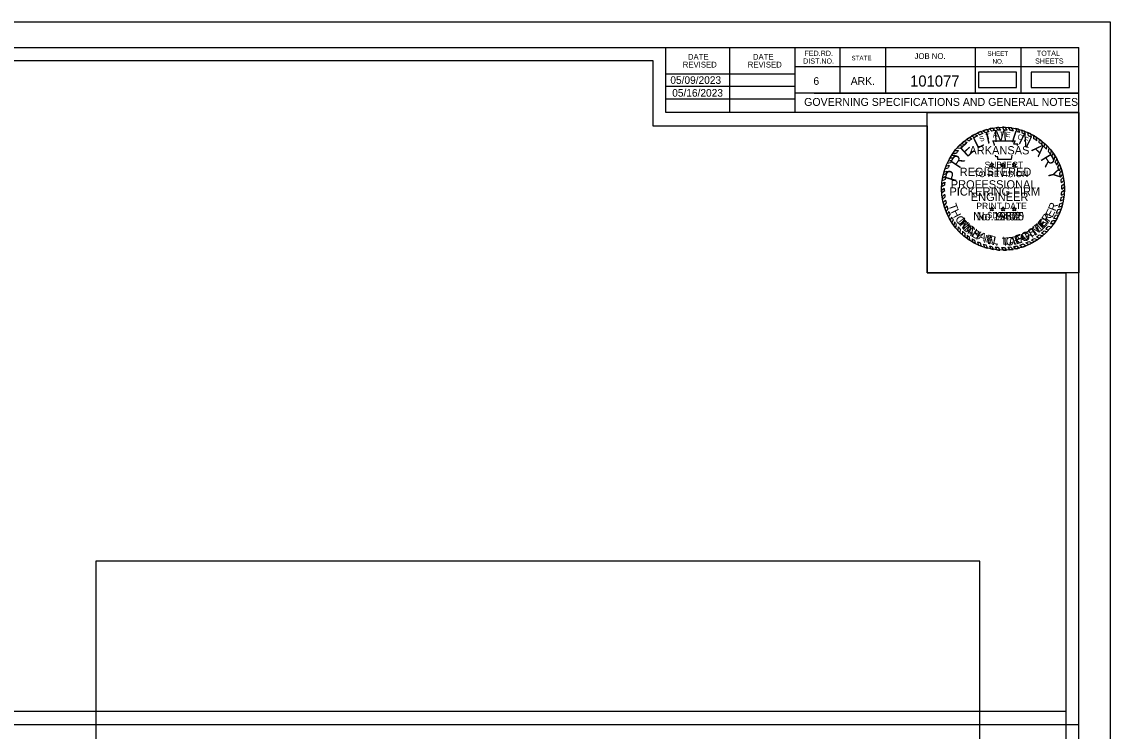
# Model space of a CAD drawing. Extents: x 1369900 to 1370234, y 380116 to 380330.
# Drawn here: x 1370068.5 to 1370233.6, y 380221.9 to 380329.6 of the extents above; entities that cross this region are included whole.
import ezdxf

# ---------------------------------------------------------------- set-up
doc = ezdxf.new("R2010")
doc.units = 0
for name, color, linetype in [('Default', 7, 'Continuous'), ('R_Border', 7, 'Continuous'), ('R_Border Notes', 7, 'Continuous'), ('R_Border Plan-Plan', 7, 'Continuous'), ('R_No Plot', 7, 'Continuous'), ('R_Revision Date Text', 7, 'Continuous'), ('STAMP_PE_CRAFTON', 7, 'Continuous'), ('STAMP_PE_FOSTER', 7, 'Continuous'), ('STAMP_PE_SEAL-INFO', 7, 'Continuous'), ('STAMP_PE_TAEGTMEYER', 7, 'Continuous'), ('STAMP_PE_TXT', 7, 'Continuous'), ('STAMP_PRELIMINARY', 7, 'Continuous')]:
    doc.layers.add(name, color=color, linetype=linetype)

msp = doc.modelspace()

# ---------------------------------------------------------------- linework, layer by layer
at = {"layer": 'Default'}
for points in [[(1370213.62, 380319.59), (1370219.42, 380319.59), (1370219.42, 380321.88), (1370213.62, 380321.88)], [(1370221.64, 380319.6), (1370227.44, 380319.6), (1370227.44, 380321.89), (1370221.64, 380321.89)], [(1370079.79, 380198.13), (1370213.84, 380198.13), (1370213.84, 380247.72), (1370079.79, 380247.72)]]:
    msp.add_lwpolyline(points, close=True, dxfattribs=at)
at = {"layer": 'R_Border'}
for p, q in [((1369912.68, 380325.66), (1370228.86, 380325.66)), ((1370166.22, 380315.78), (1370166.22, 380325.66)), ((1370175.9, 380315.78), (1370175.9, 380325.66)), ((1370185.76, 380325.66), (1370185.76, 380315.78)), ((1370192.6, 380325.66), (1370192.6, 380318.72)), ((1370199.54, 380325.66), (1370199.54, 380318.72)), ((1370213.12, 380325.66), (1370213.12, 380318.72)), ((1370220.06, 380325.66), (1370220.06, 380318.72)), ((1370228.86, 380120.2), (1370228.86, 380325.66)), ((1370228.86, 380322.72), (1370185.76, 380322.72)), ((1370228.86, 380322.74), (1370228.86, 380322.74)), ((1370166.22, 380321.64), (1370185.76, 380321.64)), ((1370166.22, 380319.78), (1370185.76, 380319.78)), ((1370166.22, 380317.84), (1370185.76, 380317.84)), ((1370228.86, 380318.72), (1370185.76, 380318.72)), ((1370188.72, 380318.72), (1370228.86, 380318.72)), ((1370228.86, 380315.78), (1370166.22, 380315.78))]:
    msp.add_line(p, q, dxfattribs=at)
at = {"layer": 'R_Border Plan-Plan'}
msp.add_line((1369912.68, 380222.93), (1370228.86, 380222.93), dxfattribs=at)
at = {"layer": 'R_No Plot'}
for points in [[(1369900.27, 380329.55), (1370233.61, 380329.55), (1370233.61, 380116.21), (1369900.27, 380116.21)], [(1370226.86, 380224.93), (1369914.68, 380224.93), (1369914.68, 380323.66), (1370164.22, 380323.66), (1370164.22, 380313.78), (1370181.76, 380313.78), (1370205.86, 380313.78), (1370205.86, 380291.44), (1370226.86, 380291.44)], [(1369914.68, 380323.66), (1370164.22, 380323.66), (1370164.22, 380313.78), (1370181.76, 380313.78), (1370205.86, 380313.78), (1370205.86, 380291.44), (1370226.86, 380291.44), (1370226.86, 380122.2), (1369914.68, 380122.2)], [(1370205.86, 380315.78), (1370228.86, 380315.78), (1370228.86, 380291.44), (1370205.86, 380291.44)]]:
    msp.add_lwpolyline(points, close=True, dxfattribs=at)
at = {"layer": 'STAMP_PE_SEAL-INFO'}
for p, q in [((1370213.46, 380312.69), (1370213.85, 380312.41)), ((1370213.97, 380312.9), (1370214.27, 380312.58)), ((1370214.32, 380313.03), (1370214.7, 380312.73)), ((1370214.91, 380313.21), (1370215.2, 380312.87)), ((1370215.3, 380313.31), (1370215.65, 380312.97)), ((1370215.78, 380313.41), (1370216.08, 380313.04)), ((1370216.3, 380313.48), (1370216.58, 380313.1)), ((1370217.03, 380313.13), (1370216.72, 380313.52)), ((1370217.53, 380313.13), (1370217.25, 380313.54)), ((1370217.99, 380313.11), (1370217.73, 380313.53)), ((1370218.49, 380313.06), (1370218.2, 380313.5)), ((1370218.92, 380312.99), (1370218.66, 380313.45)), ((1370219.48, 380312.88), (1370219.31, 380313.34)), ((1370219.88, 380312.77), (1370219.72, 380313.24)), ((1370220.33, 380312.62), (1370220.19, 380313.1)), ((1370220.75, 380312.46), (1370220.61, 380312.96)), ((1370221.21, 380312.26), (1370221.11, 380312.75)), ((1370211.06, 380311.09), (1370211.52, 380310.95)), ((1370211.4, 380311.39), (1370211.93, 380311.29)), ((1370211.78, 380311.72), (1370212.23, 380311.51)), ((1370212.2, 380311.98), (1370212.64, 380311.78)), ((1370212.59, 380312.23), (1370213.02, 380312)), ((1370213.03, 380312.48), (1370213.5, 380312.25)), ((1370215.83, 380311.51), (1370219.18, 380311.51)), ((1370215.95, 380311.2), (1370215.83, 380311.51)), ((1370216.06, 380310.9), (1370215.95, 380311.2)), ((1370219.18, 380311.51), (1370218.95, 380311.02)), ((1370218.95, 380311.02), (1370219.58, 380311.02)), ((1370219.58, 380311.02), (1370219.44, 380310.79)), ((1370221.66, 380312.03), (1370221.57, 380312.53)), ((1370222.05, 380311.8), (1370222.01, 380312.3)), ((1370222.48, 380311.51), (1370222.45, 380312.03)), ((1370222.84, 380311.25), (1370222.88, 380311.73)), ((1370223.29, 380310.87), (1370223.31, 380311.4)), ((1370223.6, 380310.58), (1370223.67, 380311.08)), ((1370209.54, 380309.29), (1370210.06, 380309.33)), ((1370209.78, 380309.64), (1370210.28, 380309.63)), ((1370210.05, 380310.01), (1370210.6, 380310.03)), ((1370210.4, 380310.42), (1370210.92, 380310.38)), ((1370210.72, 380310.76), (1370211.27, 380310.72)), ((1370216.07, 380310.79), (1370216.06, 380310.9)), ((1370216.26, 380309.08), (1370216.23, 380309.3)), ((1370218.69, 380309.3), (1370218.62, 380308.99)), ((1370223.96, 380310.21), (1370224.03, 380310.73)), ((1370224.23, 380309.89), (1370224.37, 380310.36)), ((1370224.56, 380309.47), (1370224.69, 380309.97)), ((1370224.78, 380309.16), (1370224.96, 380309.62)), ((1370208.69, 380307.65), (1370209.2, 380307.8)), ((1370208.88, 380308.08), (1370209.38, 380308.19)), ((1370209.06, 380308.47), (1370209.56, 380308.54)), ((1370209.29, 380308.89), (1370209.78, 380308.91)), ((1370216.57, 380309.08), (1370216.26, 380309.08)), ((1370216.57, 380308.65), (1370216.57, 380309.08)), ((1370218.6, 380308.65), (1370216.57, 380308.65)), ((1370218.62, 380308.99), (1370218.6, 380308.65)), ((1370225.09, 380308.66), (1370225.27, 380309.15)), ((1370225.29, 380308.3), (1370225.51, 380308.74)), ((1370225.52, 380307.81), (1370225.74, 380308.3)), ((1370225.66, 380307.47), (1370225.92, 380307.91)), ((1370208.64, 380306.09), (1370208.18, 380305.84)), ((1370208.28, 380306.33), (1370208.75, 380306.53)), ((1370208.38, 380306.74), (1370208.86, 380306.91)), ((1370208.54, 380307.24), (1370209.03, 380307.38)), ((1370225.85, 380306.93), (1370226.12, 380307.4)), ((1370225.96, 380306.56), (1370226.25, 380307.01)), ((1370226.09, 380306), (1370226.41, 380306.45)), ((1370226.16, 380305.62), (1370226.52, 380305.98)), ((1370208.46, 380304.77), (1370208.04, 380304.51)), ((1370208.5, 380305.19), (1370208.06, 380304.91)), ((1370208.56, 380305.63), (1370208.11, 380305.41)), ((1370226.23, 380305.11), (1370226.6, 380305.45)), ((1370226.26, 380304.69), (1370226.65, 380304.99)), ((1370226.27, 380304.18), (1370226.68, 380304.5)), ((1370208.45, 380304.27), (1370208.04, 380303.94)), ((1370208.45, 380303.87), (1370208.06, 380303.54)), ((1370208.49, 380303.37), (1370208.12, 380303.01)), ((1370208.54, 380302.94), (1370208.18, 380302.57)), ((1370226.17, 380302.88), (1370226.62, 380303.1)), ((1370226.22, 380303.27), (1370226.66, 380303.52)), ((1370226.26, 380303.77), (1370226.68, 380304.05)), ((1370208.62, 380302.48), (1370208.28, 380302.12)), ((1370208.71, 380302.06), (1370208.4, 380301.65)), ((1370208.83, 380301.62), (1370208.54, 380301.2)), ((1370208.98, 380301.19), (1370208.69, 380300.78)), ((1370225.69, 380301.05), (1370226.17, 380301.18)), ((1370225.83, 380301.43), (1370226.32, 380301.63)), ((1370225.97, 380301.93), (1370226.45, 380302.13)), ((1370226.08, 380302.38), (1370226.54, 380302.57)), ((1370209.14, 380300.77), (1370208.88, 380300.35)), ((1370209.31, 380300.38), (1370209.09, 380299.92)), ((1370209.55, 380299.93), (1370209.36, 380299.44)), ((1370209.78, 380299.52), (1370209.6, 380299.05)), ((1370224.87, 380299.42), (1370225.35, 380299.42)), ((1370225.04, 380299.7), (1370225.55, 380299.76)), ((1370225.32, 380300.2), (1370225.8, 380300.27)), ((1370225.48, 380300.54), (1370225.97, 380300.63)), ((1370209.99, 380299.21), (1370209.88, 380298.66)), ((1370210.27, 380298.82), (1370210.17, 380298.29)), ((1370210.57, 380298.44), (1370210.48, 380297.92)), ((1370210.87, 380298.1), (1370210.81, 380297.58)), ((1370211.2, 380297.78), (1370211.17, 380297.25)), ((1370223.59, 380297.84), (1370224.03, 380297.7)), ((1370223.84, 380298.1), (1370224.32, 380298.01)), ((1370224.23, 380298.53), (1370224.69, 380298.45)), ((1370224.53, 380298.93), (1370225.04, 380298.93)), ((1370211.54, 380297.47), (1370211.54, 380296.94)), ((1370211.9, 380297.17), (1370211.92, 380296.65)), ((1370212.24, 380296.92), (1370212.28, 380296.4)), ((1370212.67, 380296.64), (1370212.73, 380296.13)), ((1370213.02, 380296.43), (1370213.11, 380295.92)), ((1370213.5, 380296.19), (1370213.65, 380295.66)), ((1370221.28, 380296.22), (1370221.77, 380296)), ((1370221.69, 380296.43), (1370222.11, 380296.2)), ((1370222.11, 380296.67), (1370222.56, 380296.48)), ((1370222.45, 380296.9), (1370222.89, 380296.71)), ((1370222.91, 380297.24), (1370223.38, 380297.1)), ((1370223.18, 380297.47), (1370223.65, 380297.34)), ((1370213.87, 380296.02), (1370214.04, 380295.51)), ((1370214.36, 380295.82), (1370214.57, 380295.32)), ((1370214.77, 380295.69), (1370215, 380295.2)), ((1370215.28, 380295.55), (1370215.49, 380295.08)), ((1370215.68, 380295.47), (1370215.92, 380295.01)), ((1370216.18, 380295.38), (1370216.42, 380294.94)), ((1370216.61, 380295.34), (1370216.89, 380294.91)), ((1370217.1, 380295.31), (1370217.4, 380294.9)), ((1370217.56, 380295.31), (1370217.9, 380294.91)), ((1370218.08, 380295.33), (1370218.4, 380294.95)), ((1370218.52, 380295.38), (1370218.89, 380295.02)), ((1370218.96, 380295.45), (1370219.35, 380295.11)), ((1370219.45, 380295.55), (1370219.83, 380295.23)), ((1370219.91, 380295.68), (1370220.33, 380295.38)), ((1370220.41, 380295.84), (1370220.85, 380295.57)), ((1370220.82, 380296.01), (1370221.25, 380295.75))]:
    msp.add_line(p, q, dxfattribs=at)
for radius, start, end in [(9.32, 111.3124, 114.7026), (8.91, 110.3086, 113.1659), (9.32, 105.2339, 109.0352), (8.91, 104.0352, 107.3615), (9.32, 99.7525, 102.7765), (8.91, 98.258, 101.0329), (9.32, 93.9381, 96.5517), (8.91, 92.1102, 95.0367), (9.32, 87.7298, 90.6707), (8.91, 85.9628, 88.9097), (9.32, 81.9732, 84.8236), (8.91, 79.9264, 82.696), (9.32, 75.3125, 77.9426), (8.91, 73.5575, 76.2314), (9.32, 69.6061, 72.3058), (8.91, 67.6248, 70.504), (9.32, 63.1329, 66.2704), (9.32, 129.7326, 132.5376), (8.91, 127.5297, 130.9683), (9.32, 123.6199, 126.5906), (8.91, 121.9746, 125.11), (9.32, 117.6544, 120.8099), (8.91, 115.6869, 119.1583), (8.91, 61.1558, 64.3784), (9.32, 56.9003, 60.0942), (8.91, 54.9238, 58.2702), (8.91, 48.3016, 52.0395), (9.32, 50.3492, 53.7159), (9.32, 44.3405, 47.3929), (9.32, 147.0072, 149.899), (9.32, 141.6056, 144.4486), (8.91, 145.0197, 148.2104), (8.91, 139.301, 142.5873), (9.32, 135.4021, 138.3031), (8.91, 133.1331, 136.2562), (8.91, 42.2212, 45.5512), (8.91, 36.135, 39.5311), (9.32, 38.1247, 41.2316), (9.32, 31.9614, 35.4294), (9.32, 158.4077, 161.0701), (9.32, 152.864, 155.5189), (8.91, 156.3402, 159.2319), (8.91, 151.0315, 153.573), (8.91, 29.9032, 33.6645), (8.91, 23.7732, 27.2211), (9.32, 25.9391, 29.0125), (9.32, 19.9538, 23.3141), (9.32, 164.3068, 166.894), (8.91, 167.9048, 170.9039), (8.91, 162.4331, 165.0013), (8.91, 17.6802, 21.4251), (8.91, 11.5444, 15.2364), (9.32, 13.8421, 17.4447), (9.32, 7.5852, 10.8621), (9.32, 175.7409, 178.2066), (9.32, 170.0003, 172.6878), (8.91, 173.73, 176.4734), (8.91, 5.7599, 9.0606), (8.91, 359.7329, 3.0639), (9.32, 1.7215, 4.7268), (9.32, 181.7251, 184.1626), (9.32, 187.4204, 190.1927), (8.91, 179.6454, 182.2633), (8.91, 185.4539, 188.234), (8.91, 348.0778, 351.3435), (8.91, 353.8632, 357.1274), (9.32, 349.8305, 353.0885), (9.32, 355.7156, 358.9569), (9.32, 193.0369, 195.9973), (9.32, 198.8967, 201.6281), (8.91, 191.2274, 193.9858), (8.91, 196.9675, 199.8353), (8.91, 335.6038, 339.1858), (8.91, 341.777, 345.0925), (9.32, 337.3837, 340.9933), (9.32, 343.8925, 347.035), (9.32, 204.5479, 207.4328), (8.91, 202.7761, 205.4791), (9.32, 210.8636, 213.6571), (8.91, 208.7883, 211.7934), (8.91, 323.5851, 327.4407), (8.91, 329.5549, 333.2076), (9.32, 325.4405, 328.9872), (9.32, 331.4037, 334.9332), (9.32, 216.6115, 219.491), (8.91, 214.1838, 217.2747), (9.32, 222.48, 225.3801), (8.91, 220.3909, 223.3056), (8.91, 226.2494, 229.2407), (8.91, 310.7744, 314.3161), (8.91, 316.6531, 320.3711), (9.32, 318.2846, 321.8043), (9.32, 228.3665, 231.348), (8.91, 232.229, 234.9336), (9.32, 234.295, 236.9452), (8.91, 238.2223, 240.8353), (9.32, 240.1977, 242.8613), (8.91, 244.3204, 246.9486), (8.91, 292.8745, 296.1185), (8.91, 299.0768, 302.1724), (9.32, 300.621, 303.8703), (8.91, 304.823, 308.5143), (9.32, 306.3721, 310.208), (9.32, 312.4518, 315.6633), (9.32, 246.576, 249.1558), (8.91, 250.3491, 253.1216), (9.32, 252.5967, 255.3252), (8.91, 256.505, 259.1192), (9.32, 258.4433, 261.1398), (8.91, 262.3783, 265.2012), (9.32, 264.1978, 267.1009), (8.91, 268.3215, 271.277), (9.32, 270.2548, 273.3361), (8.91, 274.6157, 277.4486), (9.32, 276.4239, 279.4357), (8.91, 280.3459, 283.5814), (9.32, 282.3199, 285.3702), (8.91, 286.6423, 289.9783), (9.32, 288.5709, 291.9733), (9.32, 294.6481, 298.2166)]:
    msp.add_arc((1370217.36, 380304.22), radius, start, end, dxfattribs=at)
at = {"layer": 'STAMP_PE_TXT'}
for p, q in [((1370215.54, 380307.79), (1370215.34, 380307.93)), ((1370215.34, 380307.93), (1370215.59, 380307.93)), ((1370215.46, 380307.56), (1370215.54, 380307.79)), ((1370215.66, 380307.7), (1370215.46, 380307.56)), ((1370215.59, 380307.93), (1370215.66, 380308.17)), ((1370215.66, 380308.17), (1370215.74, 380307.93)), ((1370215.86, 380307.56), (1370215.66, 380307.7)), ((1370215.74, 380307.93), (1370215.98, 380307.93)), ((1370215.98, 380307.93), (1370215.78, 380307.79)), ((1370215.78, 380307.79), (1370215.86, 380307.56)), ((1370217.24, 380307.79), (1370217.04, 380307.93)), ((1370217.04, 380307.93), (1370217.28, 380307.93)), ((1370217.16, 380307.56), (1370217.24, 380307.79)), ((1370217.36, 380307.7), (1370217.16, 380307.56)), ((1370217.28, 380307.93), (1370217.36, 380308.17)), ((1370217.36, 380308.17), (1370217.44, 380307.93)), ((1370217.56, 380307.56), (1370217.36, 380307.7)), ((1370217.44, 380307.93), (1370217.68, 380307.93)), ((1370217.68, 380307.93), (1370217.48, 380307.79)), ((1370217.48, 380307.79), (1370217.56, 380307.56)), ((1370218.94, 380307.79), (1370218.74, 380307.93)), ((1370218.74, 380307.93), (1370218.98, 380307.93)), ((1370218.86, 380307.56), (1370218.94, 380307.79)), ((1370219.06, 380307.7), (1370218.86, 380307.56)), ((1370218.98, 380307.93), (1370219.06, 380308.17)), ((1370219.06, 380308.17), (1370219.13, 380307.93)), ((1370219.26, 380307.56), (1370219.06, 380307.7)), ((1370219.13, 380307.93), (1370219.38, 380307.93)), ((1370219.38, 380307.93), (1370219.18, 380307.79)), ((1370219.18, 380307.79), (1370219.26, 380307.56)), ((1370215.54, 380301.08), (1370215.34, 380301.23)), ((1370215.34, 380301.23), (1370215.59, 380301.23)), ((1370215.46, 380300.85), (1370215.54, 380301.08)), ((1370215.59, 380301.23), (1370215.66, 380301.46)), ((1370215.66, 380301.46), (1370215.74, 380301.23)), ((1370215.74, 380301.23), (1370215.98, 380301.23)), ((1370215.98, 380301.23), (1370215.78, 380301.08)), ((1370215.78, 380301.08), (1370215.86, 380300.85)), ((1370217.24, 380301.08), (1370217.04, 380301.23)), ((1370217.04, 380301.23), (1370217.28, 380301.23)), ((1370217.16, 380300.85), (1370217.24, 380301.08)), ((1370217.28, 380301.23), (1370217.36, 380301.46)), ((1370217.36, 380301.46), (1370217.44, 380301.23)), ((1370217.44, 380301.23), (1370217.68, 380301.23)), ((1370217.68, 380301.23), (1370217.48, 380301.08)), ((1370217.48, 380301.08), (1370217.56, 380300.85)), ((1370218.94, 380301.08), (1370218.74, 380301.23)), ((1370218.74, 380301.23), (1370218.98, 380301.23)), ((1370218.86, 380300.85), (1370218.94, 380301.08)), ((1370218.98, 380301.23), (1370219.06, 380301.46)), ((1370219.06, 380301.46), (1370219.13, 380301.23)), ((1370219.13, 380301.23), (1370219.38, 380301.23)), ((1370219.38, 380301.23), (1370219.18, 380301.08)), ((1370219.18, 380301.08), (1370219.26, 380300.85)), ((1370215.66, 380300.99), (1370215.46, 380300.85)), ((1370215.86, 380300.85), (1370215.66, 380300.99)), ((1370217.36, 380300.99), (1370217.16, 380300.85)), ((1370217.56, 380300.85), (1370217.36, 380300.99)), ((1370219.06, 380300.99), (1370218.86, 380300.85)), ((1370219.26, 380300.85), (1370219.06, 380300.99))]:
    msp.add_line(p, q, dxfattribs=at)
at = {"layer": 'STAMP_PRELIMINARY'}
msp.add_circle((1370217.36, 380304.22), 9.32, dxfattribs=at)

# ---------------------------------------------------------------- texts
at = {"layer": 'R_Border'}
for s, height, p in [('DATE', 0.879, (1370169.56, 380323.79)), ('DATE', 0.879, (1370179.42, 380323.79)), ('FED.RD.', 0.782, (1370187.24, 380324.38)), ('STATE', 0.684, (1370194.36, 380323.7)), ('JOB NO.', 0.879, (1370203.94, 380323.9)), ('SHEET', 0.684, (1370214.98, 380324.38)), ('TOTAL', 0.782, (1370222.5, 380324.38)), ('REVISED', 0.879, (1370168.78, 380322.61)), ('REVISED', 0.879, (1370178.64, 380322.61)), ('DIST.NO.', 0.782, (1370187.04, 380323.2)), ('NO.', 0.684, (1370215.76, 380323.2)), ('SHEETS', 0.782, (1370222.22, 380323.2)), ('6', 1.17, (1370188.6, 380319.98)), ('ARK.', 1.172, (1370194.26, 380319.98))]:
    msp.add_text(s, height=height, dxfattribs=at).set_placement(p)
at = {"layer": 'R_Border Notes'}
for s, height, p in [('101077', 1.68, (1370203.26, 380319.72)), ('GOVERNING SPECIFICATIONS AND GENERAL NOTES', 1.2, (1370187.19, 380316.79))]:
    msp.add_text(s, height=height, dxfattribs=at).set_placement(p)
at = {"layer": 'R_Revision Date Text'}
for s, p in [('05/09/2023', (1370166.9, 380320.13)), ('05/16/2023', (1370167.18, 380318.19))]:
    msp.add_text(s, height=1.15, dxfattribs=at).set_placement(p)
at = {"layer": 'STAMP_PE_CRAFTON'}
for s, rotation, p in [('T', 310.7442, (1370210.33, 380299.12)), ('N', 49.2411, (1370223.64, 380298.24)), ('O', 317.6422, (1370210.99, 380298.3)), ('N', 324.4537, (1370211.84, 380297.52)), ('Y', 331.1686, (1370212.87, 380296.8)), ('F', 28.7821, (1370221.02, 380296.35)), ('T', 34.1136, (1370221.94, 380296.86)), ('O', 41.8391, (1370222.8, 380297.46)), ('N', 347.4752, (1370214.93, 380295.89)), ('C', 6.0117, (1370217.83, 380295.56)), ('R', 14.8189, (1370218.93, 380295.67)), ('A', 20.5125, (1370220.04, 380295.97)), ('.', 356.8926, (1370216.16, 380295.61))]:
    msp.add_text(s, height=1.25, rotation=rotation, dxfattribs=at).set_placement(p)
msp.add_text('No. 12370', height=1.25, dxfattribs=at).set_placement((1370212.82, 380299.42))
at = {"layer": 'STAMP_PE_FOSTER'}
for s, rotation, p in [('M', 308.339, (1370210.48, 380299.24)), ('E', 46.9613, (1370223.36, 380298.21)), ('R', 54.5031, (1370224.08, 380299.03)), ('I', 314.1842, (1370211.27, 380298.3)), ('C', 319.8733, (1370211.63, 380297.95)), ('H', 327.7235, (1370212.56, 380297.21)), ('O', 23.719, (1370220.44, 380296.3)), ('S', 31.7234, (1370221.55, 380296.83)), ('T', 39.4194, (1370222.5, 380297.46)), ('A', 335.7276, (1370213.54, 380296.63)), ('E', 343.5779, (1370214.68, 380296.16)), ('L', 350.8115, (1370215.73, 380295.88)), ('L', 1.2666, (1370217.27, 380295.73)), ('F', 15.8691, (1370219.4, 380295.97)), ('.', 6.8035, (1370218.32, 380295.79))]:
    msp.add_text(s, height=1.2, rotation=rotation, dxfattribs=at).set_placement(p)
msp.add_text('No. 9402', height=1.25, dxfattribs=at).set_placement((1370213.35, 380299.42))
at = {"layer": 'STAMP_PE_TAEGTMEYER'}
for s, rotation, p in [('T', 289.646, (1370209.05, 380301.73)), ('H', 296.7339, (1370209.41, 380300.74)), ('E', 63.0984, (1370224.81, 380299.75)), ('R', 69.57, (1370225.31, 380300.73)), ('O', 303.7708, (1370210.01, 380299.64)), ('M', 314.2033, (1370210.66, 380298.69)), ('E', 46.8094, (1370223.4, 380298)), ('Y', 53.9986, (1370224.14, 380298.81)), ('A', 321.0594, (1370211.62, 380297.72)), ('S', 327.8239, (1370212.45, 380297.08)), ('T', 31.466, (1370221.46, 380296.57)), ('M', 39.3, (1370222.36, 380297.12)), ('N', 344.2727, (1370214.35, 380296.07)), ('T', 3.0061, (1370217.22, 380295.54)), ('A', 8.9826, (1370218.27, 380295.59)), ('E', 17.6836, (1370219.31, 380295.75)), ('G', 23.3052, (1370220.36, 380296.08)), ('.', 350.6464, (1370215.56, 380295.74))]:
    msp.add_text(s, height=1.25, rotation=rotation, dxfattribs=at).set_placement(p)
msp.add_text('No. 19605', height=1.25, dxfattribs=at).set_placement((1370212.82, 380299.42))
at = {"layer": 'STAMP_PE_TXT'}
for s, rotation, p in [('T', 16.311, (1370214.88, 380311.69)), ('A', 9.0679, (1370215.84, 380311.95)), ('T', 1.8248, (1370216.83, 380312.08)), ('E', 355.2002, (1370217.74, 380312.09)), ('S', 23.5541, (1370213.96, 380311.32)), ('O', 342.2506, (1370219.47, 380311.81)), ('F', 335.0075, (1370220.43, 380311.47))]:
    msp.add_text(s, height=0.781, rotation=rotation, dxfattribs=at).set_placement(p)
for s, p in [('ARKANSAS', (1370212.25, 380309.43)), ('REGISTERED', (1370210.78, 380306.16)), ('PROFESSIONAL', (1370209.43, 380304.26)), ('ENGINEER', (1370212.47, 380302.36))]:
    msp.add_text(s, height=1.25, dxfattribs=at).set_placement(p)
at = {"layer": 'STAMP_PRELIMINARY'}
for s, rotation, p in [('I', 12.5248, (1370214.9, 380311.01)), ('M', 3.1074, (1370216, 380311.31)), ('I', 342.3164, (1370218.46, 380311.38)), ('N', 333.9382, (1370219.57, 380311.11)), ('E', 42.3578, (1370211.89, 380308.91)), ('L', 25.513, (1370213.37, 380310.25)), ('R', 56.2292, (1370210.73, 380307.18)), ('A', 315.6579, (1370221.6, 380310.08)), ('R', 301.3831, (1370222.97, 380308.77)), ('P', 73.913, (1370210.18, 380305.16)), ('Y', 283.2593, (1370224.06, 380306.98))]:
    msp.add_text(s, height=1.8, rotation=rotation, dxfattribs=at).set_placement(p)
for s, height, p in [('SUBJECT', 0.96, (1370214.56, 380307.37)), ('TO REVISION', 0.96, (1370212.9, 380305.98)), ('PICKERING FIRM', 1.25, (1370209.23, 380303.18)), ('PRINT DATE', 0.96, (1370213.32, 380301.13)), ('$DATE$', 0.96, (1370214.99, 380299.75))]:
    msp.add_text(s, height=height, dxfattribs=at).set_placement(p)

doc.saveas('drawing.dxf')
